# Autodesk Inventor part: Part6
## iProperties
Created: 2002-04
Part Number: Part6
Document SubType Name: Sheet Metal
Control State: 0
Master: False
Checked Out: False
Shininess: 77.0
Angle Display Precision: 2
Document Length Units: 11269
Document Angle Units: 11279
Document Time Units: 11290
Document Mass Units: 11283
Document Length Units Precision: 3
Document Angle Units Precision: 2
Compacted: True
Density: 0.0
Volumn: 0.0
Area: 0.0
PropertySet Name: Model Information
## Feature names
1. Plate1
2. Plate2
3. Bend1
4. Plate3
5. Bend2
